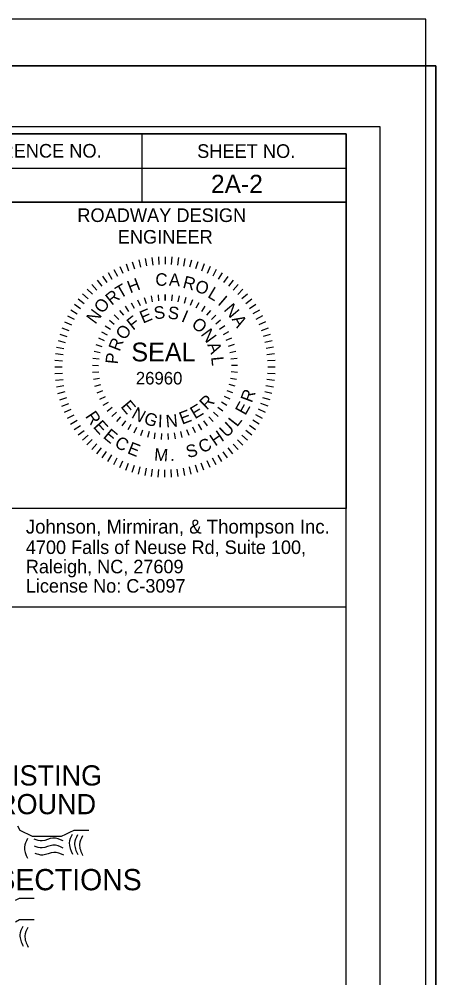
# Model space of a CAD drawing. Extents: x 2294455 to 2294795, y 719276 to 719941.
# Drawn here: x 2294763.9 to 2294794.5, y 719648.3 to 719718.8 of the extents above; entities that cross this region are included whole.
import ezdxf

# ---------------------------------------------------------------- set-up
doc = ezdxf.new("R2010")
doc.units = 0
for name, color, linetype in [('Default', 7, 'Continuous'), ('Old_Level_1', 7, 'Continuous'), ('Old_Level_2', 7, 'Continuous'), ('Sheet Data Field CELL', 7, 'Continuous'), ('Sheet Plan CELL', 7, 'Continuous'), ('Sheet Plot Border Inside CELL', 7, 'Continuous'), ('Sheet Plot Border Outside CELL', 7, 'Continuous'), ('Sheet Typical CELL', 7, 'Continuous'), ('Typical Hinge Slope Arterial CELL', 7, 'Continuous')]:
    doc.layers.add(name, color=color, linetype=linetype)

msp = doc.modelspace()

# ---------------------------------------------------------------- linework, layer by layer
at = {"layer": 'Default'}
for p, q in [((2294771.754, 719700.78), (2294771.949, 719700.263)), ((2294772.216, 719700.939), (2294772.379, 719700.411)), ((2294772.688, 719701.07), (2294772.819, 719700.533)), ((2294773.166, 719701.172), (2294773.265, 719700.629)), ((2294773.65, 719701.245), (2294773.715, 719700.697)), ((2294774.137, 719701.288), (2294774.169, 719700.738)), ((2294774.626, 719701.303), (2294774.626, 719700.751)), ((2294775.116, 719701.288), (2294775.082, 719700.737)), ((2294775.603, 719701.243), (2294775.536, 719700.695)), ((2294776.086, 719701.169), (2294775.987, 719700.626)), ((2294776.564, 719701.066), (2294776.432, 719700.53)), ((2294777.036, 719700.935), (2294776.871, 719700.406)), ((2294777.498, 719700.774), (2294777.301, 719700.258)), ((2294770.434, 719700.139), (2294770.72, 719699.666)), ((2294770.861, 719700.379), (2294771.117, 719699.889)), ((2294771.302, 719700.592), (2294771.527, 719700.089)), ((2294777.95, 719700.586), (2294777.723, 719700.083)), ((2294778.39, 719700.372), (2294778.133, 719699.883)), ((2294778.816, 719700.131), (2294778.529, 719699.659)), ((2294769.63, 719699.584), (2294769.969, 719699.149)), ((2294770.023, 719699.873), (2294770.337, 719699.419)), ((2294779.226, 719699.865), (2294778.912, 719699.411)), ((2294779.62, 719699.575), (2294779.279, 719699.14)), ((2294768.897, 719698.936), (2294769.286, 719698.545)), ((2294769.253, 719699.271), (2294769.619, 719698.857)), ((2294779.996, 719699.261), (2294779.629, 719698.848)), ((2294780.351, 719698.925), (2294779.961, 719698.535)), ((2294768.247, 719698.204), (2294768.681, 719697.864)), ((2294768.561, 719698.58), (2294768.974, 719698.213)), ((2294772.142, 719697.932), (2294772.355, 719697.525)), ((2294772.61, 719698.15), (2294772.783, 719697.723)), ((2294773.097, 719698.32), (2294773.228, 719697.879)), ((2294773.598, 719698.443), (2294773.686, 719697.991)), ((2294774.108, 719698.517), (2294774.152, 719698.059)), ((2294774.624, 719698.541), (2294774.623, 719698.082)), ((2294774.623, 719698.082), (2294774.624, 719698.541)), ((2294775.139, 719698.516), (2294775.094, 719698.058)), ((2294775.649, 719698.441), (2294775.561, 719697.99)), ((2294776.15, 719698.317), (2294776.018, 719697.876)), ((2294776.637, 719698.146), (2294776.463, 719697.719)), ((2294777.104, 719697.928), (2294776.89, 719697.521)), ((2294780.687, 719698.569), (2294780.273, 719698.203)), ((2294781, 719698.192), (2294780.565, 719697.853)), ((2294767.691, 719697.4), (2294768.163, 719697.113)), ((2294767.957, 719697.811), (2294768.411, 719697.497)), ((2294771.279, 719697.368), (2294771.568, 719697.009)), ((2294771.697, 719697.671), (2294771.949, 719697.286)), ((2294777.549, 719697.666), (2294777.296, 719697.281)), ((2294777.966, 719697.362), (2294777.677, 719697.003)), ((2294781.289, 719697.798), (2294780.835, 719697.485)), ((2294781.555, 719697.387), (2294781.082, 719697.102)), ((2294767.236, 719696.534), (2294767.739, 719696.307)), ((2294767.45, 719696.974), (2294767.939, 719696.717)), ((2294770.542, 719696.649), (2294770.893, 719696.352)), ((2294770.893, 719697.027), (2294771.215, 719696.697)), ((2294778.351, 719697.02), (2294778.029, 719696.69)), ((2294778.702, 719696.642), (2294778.351, 719696.345)), ((2294781.795, 719696.961), (2294781.305, 719696.704)), ((2294782.008, 719696.52), (2294781.505, 719696.295)), ((2294767.047, 719696.082), (2294767.564, 719695.886)), ((2294769.956, 719695.802), (2294770.357, 719695.577)), ((2294770.228, 719696.24), (2294770.606, 719695.977)), ((2294779.016, 719696.232), (2294778.637, 719695.97)), ((2294782.196, 719696.068), (2294781.679, 719695.872)), ((2294766.756, 719695.148), (2294767.292, 719695.017)), ((2294766.887, 719695.62), (2294767.415, 719695.456)), ((2294769.726, 719695.339), (2294770.148, 719695.155)), ((2294779.287, 719695.794), (2294778.885, 719695.569)), ((2294779.515, 719695.33), (2294779.093, 719695.147)), ((2294782.355, 719695.606), (2294781.827, 719695.442)), ((2294782.486, 719695.134), (2294781.949, 719695.003)), ((2294766.652, 719694.67), (2294767.195, 719694.571)), ((2294769.543, 719694.857), (2294769.981, 719694.715)), ((2294779.697, 719694.848), (2294779.259, 719694.707)), ((2294782.588, 719694.656), (2294782.045, 719694.557)), ((2294766.534, 719693.7), (2294767.085, 719693.666)), ((2294766.579, 719694.187), (2294767.127, 719694.12)), ((2294769.32, 719693.851), (2294769.776, 719693.796)), ((2294769.407, 719694.36), (2294769.856, 719694.26)), ((2294779.833, 719694.35), (2294779.383, 719694.251)), ((2294779.919, 719693.841), (2294779.463, 719693.787)), ((2294782.66, 719694.172), (2294782.113, 719694.106)), ((2294782.704, 719693.685), (2294782.153, 719693.652)), ((2294766.519, 719693.21), (2294767.071, 719693.21)), ((2294769.282, 719693.337), (2294769.741, 719693.325)), ((2294779.956, 719693.327), (2294779.496, 719693.316)), ((2294782.719, 719693.195), (2294782.167, 719693.196)), ((2294766.533, 719692.721), (2294767.084, 719692.754)), ((2294766.577, 719692.234), (2294767.125, 719692.3)), ((2294769.294, 719692.821), (2294769.752, 719692.854)), ((2294769.356, 719692.309), (2294769.809, 719692.386)), ((2294779.429, 719692.393), (2294779.883, 719692.316)), ((2294779.943, 719692.811), (2294779.485, 719692.845)), ((2294782.659, 719692.219), (2294782.111, 719692.286)), ((2294782.704, 719692.706), (2294782.153, 719692.74)), ((2294766.65, 719691.75), (2294767.193, 719691.849)), ((2294769.466, 719691.805), (2294769.91, 719691.925)), ((2294779.769, 719691.795), (2294779.325, 719691.916)), ((2294782.585, 719691.735), (2294782.042, 719691.835)), ((2294766.752, 719691.272), (2294767.288, 719691.403)), ((2294766.883, 719690.8), (2294767.411, 719690.964)), ((2294769.625, 719691.314), (2294770.056, 719691.477)), ((2294769.831, 719690.842), (2294770.243, 719691.045)), ((2294779.402, 719690.833), (2294778.99, 719691.037)), ((2294779.609, 719691.305), (2294779.179, 719691.468)), ((2294782.35, 719690.785), (2294781.822, 719690.95)), ((2294782.482, 719691.258), (2294781.946, 719691.389)), ((2294767.042, 719690.338), (2294767.559, 719690.533)), ((2294770.081, 719690.391), (2294770.472, 719690.632)), ((2294770.374, 719689.965), (2294770.74, 719690.244)), ((2294778.858, 719689.957), (2294778.492, 719690.237)), ((2294779.152, 719690.382), (2294778.761, 719690.625)), ((2294782.19, 719690.324), (2294781.674, 719690.52)), ((2294767.23, 719689.886), (2294767.733, 719690.111)), ((2294767.443, 719689.445), (2294767.932, 719689.701)), ((2294770.706, 719689.571), (2294771.043, 719689.883)), ((2294771.074, 719689.21), (2294771.38, 719689.555)), ((2294778.156, 719689.204), (2294777.85, 719689.549)), ((2294778.525, 719689.564), (2294778.188, 719689.877)), ((2294781.788, 719689.432), (2294781.299, 719689.689)), ((2294782.002, 719689.872), (2294781.499, 719690.098)), ((2294767.683, 719689.018), (2294768.155, 719689.304)), ((2294767.948, 719688.608), (2294768.403, 719688.921)), ((2294771.477, 719688.887), (2294771.747, 719689.259)), ((2294771.908, 719688.604), (2294772.142, 719689.001)), ((2294772.365, 719688.364), (2294772.559, 719688.781)), ((2294776.864, 719688.36), (2294776.67, 719688.777)), ((2294777.321, 719688.599), (2294777.088, 719688.996)), ((2294777.753, 719688.881), (2294777.483, 719689.253)), ((2294781.281, 719688.595), (2294780.827, 719688.909)), ((2294781.547, 719689.006), (2294781.075, 719689.292)), ((2294768.238, 719688.214), (2294768.673, 719688.553)), ((2294768.551, 719687.837), (2294768.964, 719688.203)), ((2294772.843, 719688.168), (2294772.996, 719688.603)), ((2294773.444, 719688.468), (2294773.333, 719688.021)), ((2294773.843, 719687.921), (2294773.909, 719688.376)), ((2294774.356, 719687.87), (2294774.378, 719688.33)), ((2294774.872, 719687.87), (2294774.85, 719688.33)), ((2294775.385, 719687.92), (2294775.319, 719688.375)), ((2294775.892, 719688.018), (2294775.781, 719688.466)), ((2294776.386, 719688.165), (2294776.233, 719688.6)), ((2294780.677, 719687.826), (2294780.264, 719688.192)), ((2294780.991, 719688.202), (2294780.556, 719688.542)), ((2294768.886, 719687.481), (2294769.277, 719687.871)), ((2294769.242, 719687.145), (2294769.608, 719687.558)), ((2294779.985, 719687.135), (2294779.619, 719687.548)), ((2294780.341, 719687.47), (2294779.951, 719687.861)), ((2294769.618, 719686.831), (2294769.958, 719687.265)), ((2294770.011, 719686.541), (2294770.325, 719686.995)), ((2294770.421, 719686.275), (2294770.708, 719686.747)), ((2294778.803, 719686.267), (2294778.517, 719686.74)), ((2294779.214, 719686.533), (2294778.901, 719686.987)), ((2294779.608, 719686.822), (2294779.268, 719687.257)), ((2294770.848, 719686.034), (2294771.105, 719686.523)), ((2294771.288, 719685.82), (2294771.514, 719686.323)), ((2294771.74, 719685.631), (2294771.936, 719686.148)), ((2294772.201, 719685.471), (2294772.366, 719685.999)), ((2294777.022, 719685.467), (2294776.858, 719685.995)), ((2294777.484, 719685.626), (2294777.288, 719686.143)), ((2294777.936, 719685.814), (2294777.711, 719686.317)), ((2294778.376, 719686.027), (2294778.12, 719686.516)), ((2294772.674, 719685.34), (2294772.805, 719685.876)), ((2294773.151, 719685.237), (2294773.251, 719685.779)), ((2294773.635, 719685.163), (2294773.702, 719685.711)), ((2294774.122, 719685.118), (2294774.156, 719685.669)), ((2294774.611, 719685.103), (2294774.612, 719685.655)), ((2294775.101, 719685.117), (2294775.068, 719685.668)), ((2294775.588, 719685.161), (2294775.522, 719685.709)), ((2294776.071, 719685.234), (2294775.973, 719685.777)), ((2294776.55, 719685.336), (2294776.419, 719685.872))]:
    msp.add_line(p, q, dxfattribs=at)
msp.add_lwpolyline([(2294454.524, 719715.329), (2294794.524, 719715.329), (2294794.524, 719495.329), (2294454.524, 719495.329)], close=True, dxfattribs=at)
at = {"layer": 'Old_Level_1'}
msp.add_lwpolyline([(2294747.917, 719675.6), (2294787.924, 719675.6), (2294787.924, 719682.819), (2294747.917, 719682.819)], close=True, dxfattribs=at)
at = {"layer": 'Old_Level_2'}
for points in [[(2294764.502, 719658.564), (2294764.293, 719657.944), (2294764.517, 719657.121)], [(2294764.502, 719658.564), (2294764.293, 719657.944), (2294764.517, 719657.121)], [(2294767.131, 719658.387), (2294766.382, 719658.603), (2294765.584, 719658.4), (2294765.014, 719658.529)], [(2294767.131, 719658.387), (2294766.382, 719658.603), (2294765.584, 719658.4), (2294765.014, 719658.529)], [(2294767.796, 719658.871), (2294767.582, 719658.249), (2294767.811, 719657.428)], [(2294767.796, 719658.871), (2294767.582, 719658.249), (2294767.811, 719657.428)], [(2294768.185, 719658.831), (2294767.975, 719658.208), (2294768.204, 719657.384)], [(2294768.185, 719658.831), (2294767.975, 719658.208), (2294768.204, 719657.384)], [(2294768.55, 719658.759), (2294768.338, 719658.139), (2294768.567, 719657.316)], [(2294768.55, 719658.759), (2294768.338, 719658.139), (2294768.567, 719657.316)], [(2294767.136, 719657.864), (2294766.382, 719658.077), (2294765.59, 719657.874), (2294765.018, 719658.003)], [(2294767.136, 719657.864), (2294766.382, 719658.077), (2294765.59, 719657.874), (2294765.018, 719658.003)], [(2294767.194, 719657.336), (2294766.442, 719657.548), (2294765.644, 719657.35), (2294765.072, 719657.476)], [(2294767.194, 719657.336), (2294766.442, 719657.548), (2294765.644, 719657.35), (2294765.072, 719657.476)], [(2294764.169, 719652.111), (2294763.96, 719651.489), (2294764.189, 719650.665)], [(2294764.169, 719652.111), (2294763.96, 719651.489), (2294764.189, 719650.665)], [(2294764.534, 719652.04), (2294764.323, 719651.42), (2294764.551, 719650.596)], [(2294764.534, 719652.04), (2294764.323, 719651.42), (2294764.551, 719650.596)]]:
    msp.add_spline(points, degree=3, dxfattribs=at)
at = {"layer": 'Sheet Plan CELL'}
msp.add_lwpolyline([(2294787.924, 719682.819), (2294761.64, 719682.819), (2294761.64, 719705.319), (2294787.924, 719705.319)], dxfattribs=at)
at = {"layer": 'Sheet Plot Border Inside CELL'}
msp.add_lwpolyline([(2294790.424, 719710.839), (2294457.124, 719710.839), (2294457.124, 719499.819), (2294790.424, 719499.819)], close=True, dxfattribs=at)
at = {"layer": 'Sheet Plot Border Outside CELL'}
for points in [[(2294793.79, 719718.758), (2294456.99, 719718.758), (2294456.99, 719498.758), (2294793.79, 719498.758)], [(2294794.524, 719715.329), (2294454.524, 719715.329), (2294454.524, 719495.329), (2294794.524, 719495.329)]]:
    msp.add_lwpolyline(points, close=True, dxfattribs=at)
at = {"layer": 'Sheet Typical CELL'}
for p, q in [((2294772.924, 719710.319), (2294772.924, 719705.319)), ((2294747.914, 719707.819), (2294787.924, 719707.819))]:
    msp.add_line(p, q, dxfattribs=at)
for points in [[(2294787.924, 719710.329), (2294487.924, 719710.329), (2294487.924, 719500.329), (2294787.924, 719500.329)], [(2294747.914, 719710.329), (2294787.924, 719710.329), (2294787.924, 719705.319), (2294747.914, 719705.319)], [(2294787.924, 719705.319), (2294787.924, 719705.319), (2294787.924, 719682.819), (2294787.924, 719682.819)]]:
    msp.add_lwpolyline(points, close=True, dxfattribs=at)
at = {"layer": 'Typical Hinge Slope Arterial CELL'}
for points in [[(2294763.787, 719659.501), (2294763.941, 719659.191), (2294764.249, 719659.038), (2294764.557, 719658.883), (2294764.865, 719658.73), (2294765.173, 719658.73), (2294765.481, 719658.73), (2294765.789, 719658.73), (2294766.097, 719658.73), (2294766.405, 719658.73), (2294766.713, 719658.73), (2294767.021, 719658.73), (2294767.329, 719658.883), (2294767.637, 719659.038), (2294767.945, 719659.191), (2294768.407, 719659.191), (2294768.715, 719659.191), (2294769.023, 719659.191)], [(2294763.622, 719654.029), (2294763.93, 719654.183), (2294764.392, 719654.183), (2294764.7, 719654.183), (2294765.008, 719654.183)], [(2294763.622, 719652.456), (2294763.93, 719652.609), (2294764.392, 719652.609), (2294764.7, 719652.609), (2294765.008, 719652.609)]]:
    msp.add_lwpolyline(points, dxfattribs=at)

# ---------------------------------------------------------------- texts
at = {"layer": 'Default'}
for s, height, rotation, p in [('C', 0.919, 357.30395, (2294773.889, 719699.196)), ('A', 0.919, 357.30395, (2294774.894, 719699.176)), ('T', 0.919, 30.44658, (2294771.318, 719698.207)), ('H', 0.919, 21.01464, (2294772.058, 719698.606)), ('R', 0.919, 345.29464, (2294775.868, 719699.04)), ('O', 0.919, 342.23783, (2294776.758, 719698.774)), ('R', 0.919, 38.60755, (2294770.699, 719697.693)), ('L', 0.919, 329.10154, (2294777.693, 719698.364)), ('O', 0.919, 51.66428, (2294770.032, 719697.074)), ('I', 0.919, 319.52607, (2294778.434, 719697.829)), ('N', 0.919, 310.23161, (2294778.895, 719697.396)), ('N', 0.919, 53.62371, (2294769.503, 719696.298)), ('E', 0.919, 22.89135, (2294773, 719696.385)), ('S', 0.919, 7.5951, (2294773.863, 719696.7)), ('S', 0.919, 352.29886, (2294774.782, 719696.775)), ('I', 0.919, 337.00261, (2294775.759, 719696.576)), ('F', 0.919, 38.1876, (2294772.263, 719695.865)), ('O', 0.919, 321.70637, (2294776.5, 719696.217)), ('A', 0.919, 300.46408, (2294779.501, 719696.716)), ('O', 0.919, 53.48384, (2294771.651, 719695.124)), ('N', 0.919, 306.41012, (2294777.208, 719695.601)), ('R', 0.919, 68.78009, (2294771.287, 719694.299)), ('SEAL', 1.3802, 359.94698, (2294772.146, 719693.619)), ('A', 0.919, 291.11388, (2294777.712, 719694.847)), ('P', 0.919, 84.07634, (2294771.147, 719693.387)), ('L', 0.919, 275.81763, (2294778.008, 719693.937)), ('26960', 0.9194, 359.94698, (2294772.478, 719691.927)), ('R', 0.919, 44.51187, (2294777.696, 719689.996)), ('R', 0.919, 69.61941, (2294780.999, 719690.532)), ('E', 0.919, 310.01707, (2294771.321, 719690.286)), ('N', 0.919, 330.87215, (2294772.092, 719689.519)), ('E', 0.919, 30.74079, (2294776.819, 719689.356)), ('E', 0.919, 60.94665, (2294780.525, 719689.604)), ('R', 0.919, 303.882, (2294768.723, 719689.585)), ('G', 0.919, 339.63838, (2294772.992, 719689.087)), ('I', 0.919, 357.73318, (2294774.087, 719688.791)), ('N', 0.919, 5.36284, (2294774.711, 719688.76)), ('E', 0.919, 20.7549, (2294775.875, 719688.964)), ('L', 0.919, 52.15404, (2294779.916, 719688.757)), ('E', 0.919, 311.95381, (2294769.292, 719688.79)), ('U', 0.919, 43.27141, (2294779.145, 719687.973)), ('E', 0.919, 320.59656, (2294770.015, 719688.04)), ('C', 0.919, 329.26915, (2294770.844, 719687.407)), ('H', 0.919, 34.38878, (2294778.307, 719687.353)), ('E', 0.919, 338.24163, (2294771.797, 719686.888)), ('S', 0.919, 16.5636, (2294776.318, 719686.498)), ('C', 0.919, 25.56616, (2294777.346, 719686.847)), ('M', 0.919, 356.03694, (2294773.801, 719686.332)), ('.', 0.919, 3.77928, (2294775.001, 719686.302))]:
    msp.add_text(s, height=height, rotation=rotation, dxfattribs=at).set_placement(p)
at = {"layer": 'Old_Level_1'}
for s, height, p in [('Johnson, Mirmiran, & Thompson Inc.', 1.02224, (2294764.393, 719680.97)), ('4700 Falls of Neuse Rd, Suite 100, ', 0.99303, (2294764.393, 719679.47)), ('Raleigh, NC, 27609', 0.99303, (2294764.393, 719678.051)), ('License No: C-3097', 0.99303, (2294764.393, 719676.632))]:
    msp.add_text(s, height=height, dxfattribs=at).set_placement(p)
for s, height, p in [('EXISTING', 1.4844, (2294760.733, 719662.463)), ('GROUND', 1.4844, (2294760.733, 719660.353)), ('SEE X-SECTIONS', 1.5625, (2294755.377, 719654.767))]:
    msp.add_text(s, height=height, rotation=359.99996, dxfattribs=at).set_placement(p)
at = {"layer": 'Sheet Data Field CELL'}
msp.add_text('2A-2', height=1.35, rotation=360, dxfattribs=at).set_placement((2294777.998, 719705.977))
at = {"layer": 'Sheet Plan CELL'}
for s, height, p in [('ROADWAY DESIGN', 1.00002, (2294768.176, 719703.859)), ('ENGINEER', 1, (2294771.146, 719702.269))]:
    msp.add_text(s, height=height, dxfattribs=at).set_placement(p)
at = {"layer": 'Sheet Typical CELL'}
for s, height, p in [('PROJECT REFERENCE NO.', 1.00002, (2294752.354, 719708.589)), ('SHEET NO.', 1, (2294776.984, 719708.569))]:
    msp.add_text(s, height=height, dxfattribs=at).set_placement(p)

doc.saveas('drawing.dxf')
